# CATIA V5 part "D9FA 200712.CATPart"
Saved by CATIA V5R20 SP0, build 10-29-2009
Part number: D9FA 200712
Revision: ANY
Definition: UNKNOWN
Nomenclature: D9FA 200712
Source: Unknown
Bounding box of the stored display mesh (mm): x -10 to 10, y 0.13 to 20.13, z -10 to 10
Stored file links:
  C:\Users\Utente\Desktop\IO LAVORO\3D X SITO CF\CUMSA\3D files FA\FA 200712-21\D9FA 200712.CATPart
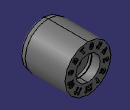
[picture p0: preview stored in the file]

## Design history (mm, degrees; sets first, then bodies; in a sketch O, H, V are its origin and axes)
Body1 "Cortar-Extruir4" (main body)
  Solid1: solid without history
